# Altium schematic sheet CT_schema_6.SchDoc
size 371 x 336 mm
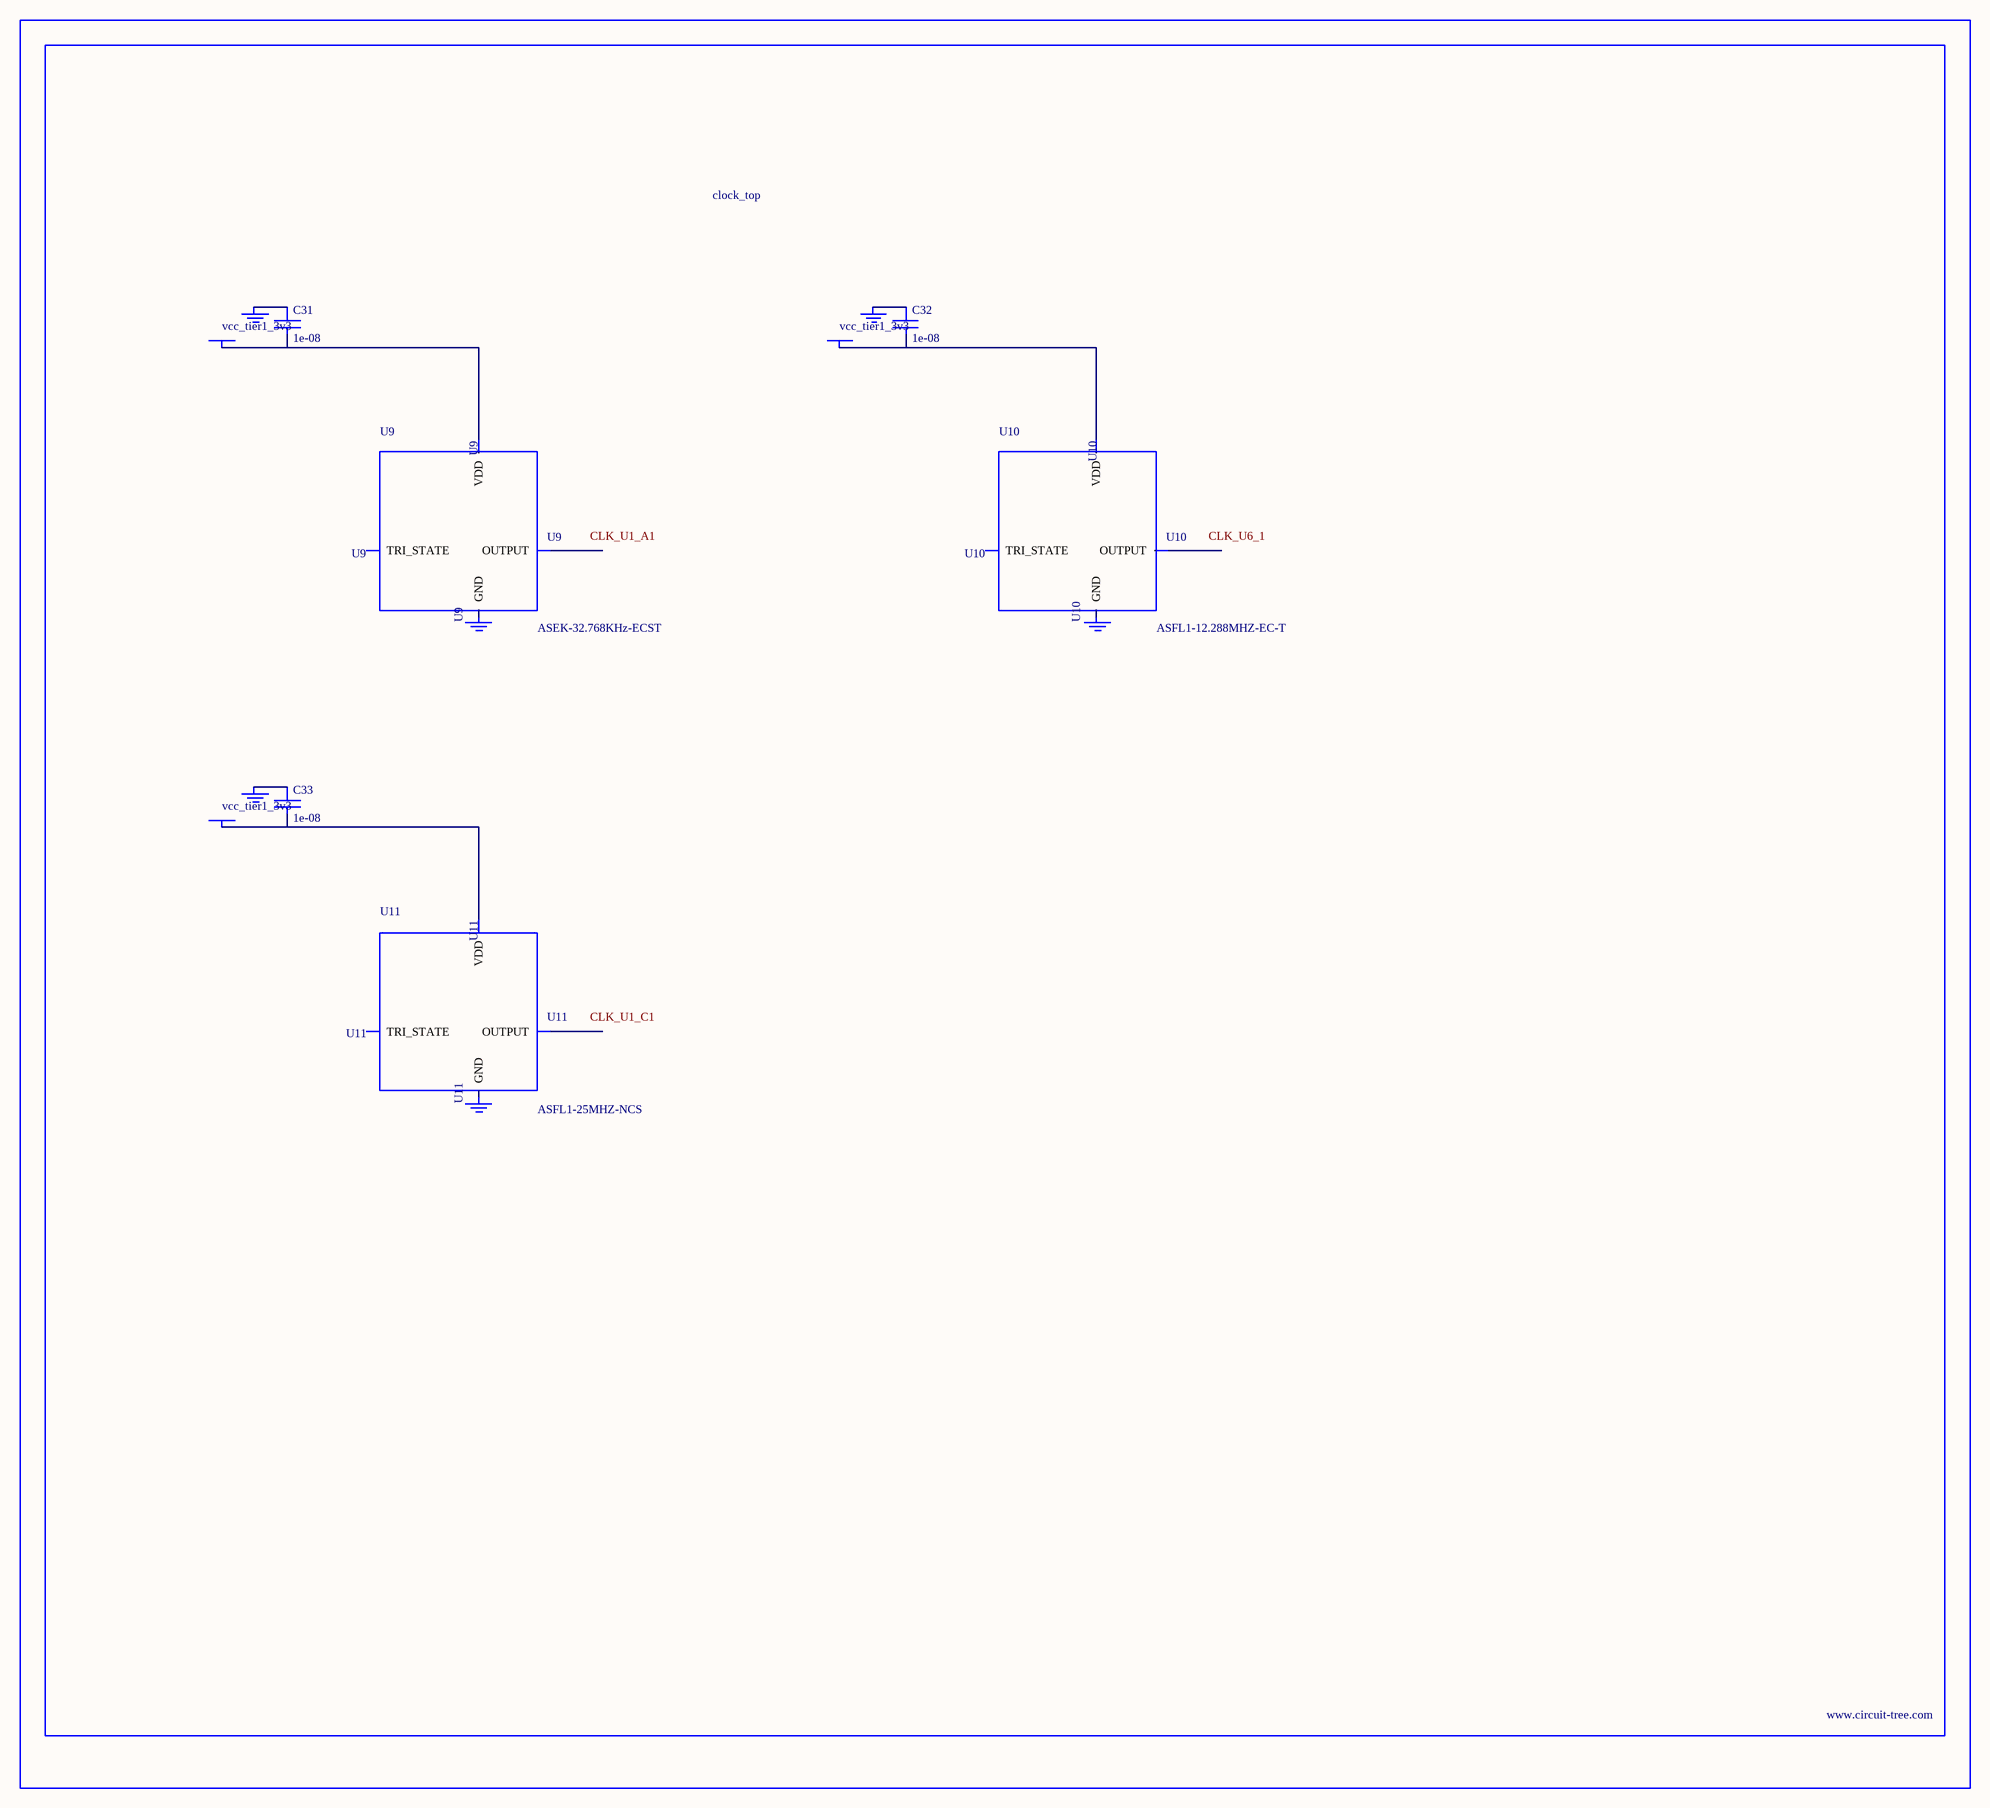
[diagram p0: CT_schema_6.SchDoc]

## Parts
BORDER5  (no value)
C31  1e-08  [C0402]
C32  1e-08  [C0402]
C33  1e-08  [C0402]
GND_INSTANCE_5_0  (no value)
GND_INSTANCE_5_1  (no value)
GND_INSTANCE_5_2  (no value)
GND_INSTANCE_5_3  (no value)
GND_INSTANCE_5_4  (no value)
GND_INSTANCE_5_5  (no value)
POWER_INSTANCE_5_0  vcc_tier1_3v3
POWER_INSTANCE_5_1  vcc_tier1_3v3
POWER_INSTANCE_5_2  vcc_tier1_3v3
U9  ASEK-32.768KHz-ECST  [ASEK]
U10  ASFL1-12.288MHZ-EC-T  [ASFL1]
U11  ASFL1-25MHZ-NCS  [ASFL1]

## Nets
NetC31_1: C31.1 GND_INSTANCE_5_0.0(GND)
NetC31_2: C31.2 POWER_INSTANCE_5_0.0(PWR) U9.4(VDD)
NetC32_1: C32.1 GND_INSTANCE_5_2.0(GND)
NetC32_2: C32.2 POWER_INSTANCE_5_1.0(PWR) U10.4(VDD)
NetC33_1: C33.1 GND_INSTANCE_5_4.0(GND)
NetC33_2: C33.2 POWER_INSTANCE_5_2.0(PWR) U11.4(VDD)

Not connected (* = marked no-connect by the designer): GND_INSTANCE_5_1 0(GND); GND_INSTANCE_5_3 0(GND); GND_INSTANCE_5_5 0(GND); U9 1(TRI_STATE) 2(GND) 3(OUTPUT); U10 1(TRI_STATE) 2(GND) 3(OUTPUT); U11 1(TRI_STATE) 2(GND) 3(OUTPUT)

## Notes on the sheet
- Labels drawn without touching a wire or pin: CLK_U1_A1, CLK_U1_C1, CLK_U6_1

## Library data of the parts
BORDER5 = BORDER_PAGE5
C31-C33 = C0402C103K3RAC
GND_INSTANCE_5_0-GND_INSTANCE_5_5 = GND
POWER_INSTANCE_5_0-POWER_INSTANCE_5_2 = PWR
